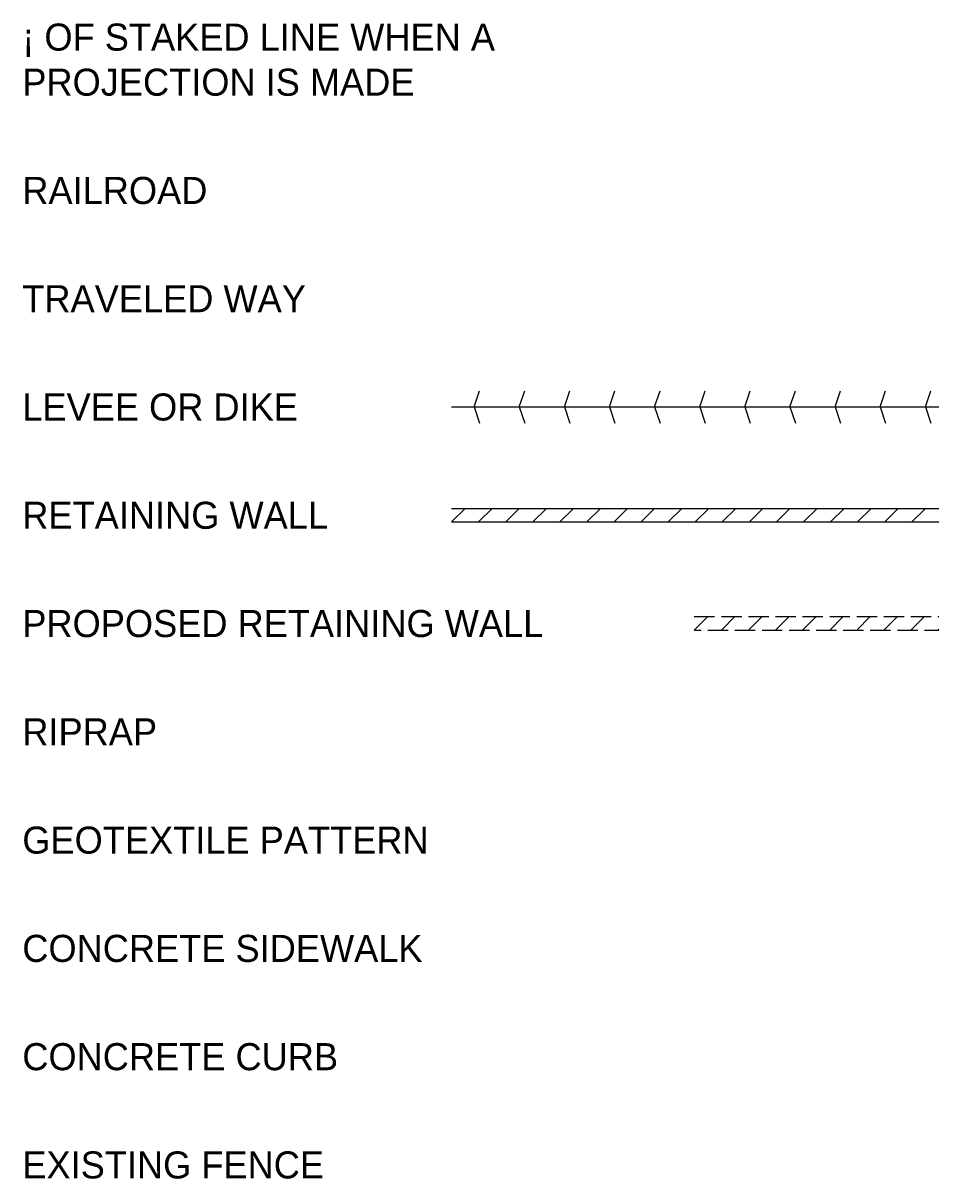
# Model space of a CAD drawing. Extents: x 49991.4 to 50021, y 49987.6 to 50011.4.
# Drawn here: x 50005.333 to 50007.362, y 49990.744 to 49993.306 of the extents above; entities that cross this region are included whole.
import ezdxf

# ---------------------------------------------------------------- set-up
doc = ezdxf.new("R2010")
doc.units = 0
doc.layers.add('Level 1', color=7, linetype='Continuous')
doc.layers.add('Level 2', color=7, linetype='Continuous')

msp = doc.modelspace()

# ---------------------------------------------------------------- linework, layer by layer
at = {"layer": 'Level 1'}
for p, q in [((50006.3322, 49992.4556), (50006.3442, 49992.4914)), ((50006.4322, 49992.4556), (50006.4442, 49992.4914)), ((50006.5322, 49992.4556), (50006.5442, 49992.4914)), ((50006.6322, 49992.4556), (50006.6442, 49992.4914)), ((50006.7322, 49992.4556), (50006.7442, 49992.4914)), ((50006.8322, 49992.4556), (50006.8442, 49992.4914)), ((50006.9322, 49992.4556), (50006.9442, 49992.4914)), ((50007.0322, 49992.4556), (50007.0442, 49992.4914)), ((50007.1322, 49992.4556), (50007.1442, 49992.4914)), ((50007.2322, 49992.4556), (50007.2442, 49992.4914)), ((50007.3322, 49992.4556), (50007.3442, 49992.4914)), ((50006.2822, 49992.4556), (50006.3822, 49992.4556)), ((50006.3322, 49992.4556), (50006.3442, 49992.4197)), ((50006.3822, 49992.4556), (50006.4822, 49992.4556)), ((50006.4322, 49992.4556), (50006.4442, 49992.4197)), ((50006.4822, 49992.4556), (50006.5822, 49992.4556)), ((50006.5322, 49992.4556), (50006.5442, 49992.4197)), ((50006.5822, 49992.4556), (50006.6822, 49992.4556)), ((50006.6322, 49992.4556), (50006.6442, 49992.4197)), ((50006.6822, 49992.4556), (50006.7822, 49992.4556)), ((50006.7322, 49992.4556), (50006.7442, 49992.4197)), ((50006.7822, 49992.4556), (50006.8822, 49992.4556)), ((50006.8322, 49992.4556), (50006.8442, 49992.4197)), ((50006.8822, 49992.4556), (50006.9822, 49992.4556)), ((50006.9322, 49992.4556), (50006.9442, 49992.4197)), ((50006.9822, 49992.4556), (50007.0822, 49992.4556)), ((50007.0322, 49992.4556), (50007.0442, 49992.4197)), ((50007.0822, 49992.4556), (50007.1822, 49992.4556)), ((50007.1322, 49992.4556), (50007.1442, 49992.4197)), ((50007.1822, 49992.4556), (50007.2822, 49992.4556)), ((50007.2322, 49992.4556), (50007.2442, 49992.4197)), ((50007.2822, 49992.4556), (50007.3622, 49992.4556)), ((50007.3322, 49992.4556), (50007.3442, 49992.4197)), ((50006.2822, 49992.2306), (50006.4022, 49992.2306)), ((50006.2822, 49992.2006), (50006.3122, 49992.2306)), ((50006.3422, 49992.2006), (50006.3722, 49992.2306)), ((50006.4022, 49992.2306), (50006.5222, 49992.2306)), ((50006.4022, 49992.2006), (50006.4322, 49992.2306)), ((50006.4622, 49992.2006), (50006.4922, 49992.2306)), ((50006.5222, 49992.2306), (50006.6422, 49992.2306)), ((50006.5222, 49992.2006), (50006.5522, 49992.2306)), ((50006.5822, 49992.2006), (50006.6122, 49992.2306)), ((50006.6422, 49992.2306), (50006.7622, 49992.2306)), ((50006.6422, 49992.2006), (50006.6722, 49992.2306)), ((50006.7022, 49992.2006), (50006.7322, 49992.2306)), ((50006.7622, 49992.2306), (50006.8822, 49992.2306)), ((50006.7622, 49992.2006), (50006.7922, 49992.2306)), ((50006.8222, 49992.2006), (50006.8522, 49992.2306)), ((50006.8822, 49992.2306), (50007.0022, 49992.2306)), ((50006.8822, 49992.2006), (50006.9122, 49992.2306)), ((50006.9422, 49992.2006), (50006.9722, 49992.2306)), ((50007.0022, 49992.2306), (50007.1222, 49992.2306)), ((50007.0022, 49992.2006), (50007.0322, 49992.2306)), ((50007.0622, 49992.2006), (50007.0922, 49992.2306)), ((50007.1222, 49992.2306), (50007.2422, 49992.2306)), ((50007.1222, 49992.2006), (50007.1522, 49992.2306)), ((50007.1822, 49992.2006), (50007.2122, 49992.2306)), ((50007.2422, 49992.2306), (50007.3622, 49992.2306)), ((50007.2422, 49992.2006), (50007.2722, 49992.2306)), ((50007.3022, 49992.2006), (50007.3322, 49992.2306)), ((50006.2822, 49992.2006), (50006.4022, 49992.2006)), ((50006.4022, 49992.2006), (50006.5222, 49992.2006)), ((50006.5222, 49992.2006), (50006.6422, 49992.2006)), ((50006.6422, 49992.2006), (50006.7622, 49992.2006)), ((50006.7622, 49992.2006), (50006.8822, 49992.2006)), ((50006.8822, 49992.2006), (50007.0022, 49992.2006)), ((50007.0022, 49992.2006), (50007.1222, 49992.2006)), ((50007.1222, 49992.2006), (50007.2422, 49992.2006)), ((50007.2422, 49992.2006), (50007.3622, 49992.2006)), ((50006.8202, 49991.9606), (50006.8502, 49991.9906)), ((50006.8202, 49991.9906), (50006.8652, 49991.9906)), ((50006.8802, 49991.9606), (50006.9102, 49991.9906)), ((50006.8802, 49991.9906), (50006.9252, 49991.9906)), ((50006.9402, 49991.9606), (50006.9702, 49991.9906)), ((50006.9402, 49991.9906), (50006.9852, 49991.9906)), ((50007.0002, 49991.9606), (50007.0302, 49991.9906)), ((50007.0002, 49991.9906), (50007.0452, 49991.9906)), ((50007.0602, 49991.9606), (50007.0902, 49991.9906)), ((50007.0602, 49991.9906), (50007.1052, 49991.9906)), ((50007.1202, 49991.9606), (50007.1502, 49991.9906)), ((50007.1202, 49991.9906), (50007.1652, 49991.9906)), ((50007.1802, 49991.9606), (50007.2102, 49991.9906)), ((50007.1802, 49991.9906), (50007.2252, 49991.9906)), ((50007.2402, 49991.9606), (50007.2702, 49991.9906)), ((50007.2402, 49991.9906), (50007.2852, 49991.9906)), ((50007.3002, 49991.9606), (50007.3302, 49991.9906)), ((50007.3002, 49991.9906), (50007.3452, 49991.9906)), ((50007.3602, 49991.9906), (50007.3622, 49991.9906)), ((50006.8202, 49991.9606), (50006.8352, 49991.9606)), ((50006.8502, 49991.9606), (50006.8952, 49991.9606)), ((50006.9102, 49991.9606), (50006.9402, 49991.9606)), ((50006.9402, 49991.9606), (50006.9552, 49991.9606)), ((50006.9702, 49991.9606), (50007.0152, 49991.9606)), ((50007.0302, 49991.9606), (50007.0602, 49991.9606)), ((50007.0602, 49991.9606), (50007.0752, 49991.9606)), ((50007.0902, 49991.9606), (50007.1352, 49991.9606)), ((50007.1502, 49991.9606), (50007.1802, 49991.9606)), ((50007.1802, 49991.9606), (50007.1952, 49991.9606)), ((50007.2102, 49991.9606), (50007.2552, 49991.9606)), ((50007.2702, 49991.9606), (50007.3002, 49991.9606)), ((50007.3002, 49991.9606), (50007.3152, 49991.9606)), ((50007.3302, 49991.9606), (50007.3622, 49991.9606)), ((50007.3602, 49991.9606), (50007.3622, 49991.9626))]:
    msp.add_line(p, q, dxfattribs=at)

# ---------------------------------------------------------------- texts
at = {"layer": 'Level 2'}
for s, height, p in [('¡ OF STAKED LINE WHEN A', 0.059999, (50005.3308, 49993.2452)), ('PROJECTION IS MADE  ', 0.059999, (50005.3308, 49993.1452)), ('RAILROAD            ', 0.059999, (50005.3308, 49992.9053)), ('TRAVELED WAY        ', 0.059999, (50005.3308, 49992.6653)), ('LEVEE OR DIKE       ', 0.06, (50005.3308, 49992.4253)), ('RETAINING WALL      ', 0.059999, (50005.3308, 49992.1853)), ('PROPOSED RETAINING WALL  ', 0.06, (50005.3308, 49991.9453)), ('RIPRAP              ', 0.059999, (50005.3308, 49991.7053)), ('GEOTEXTILE PATTERN  ', 0.059999, (50005.3308, 49991.4653)), ('CONCRETE SIDEWALK   ', 0.059999, (50005.3308, 49991.2253)), ('CONCRETE CURB       ', 0.059999, (50005.3308, 49990.9853)), ('EXISTING FENCE      ', 0.059999, (50005.3308, 49990.7453))]:
    msp.add_text(s, height=height, dxfattribs=at).set_placement(p)

doc.saveas('drawing.dxf')
